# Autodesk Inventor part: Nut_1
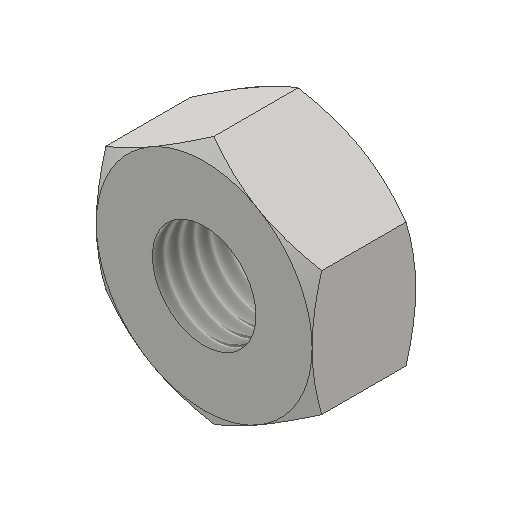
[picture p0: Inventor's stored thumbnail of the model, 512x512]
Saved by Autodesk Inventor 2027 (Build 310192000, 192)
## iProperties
Created: 2016-05
Part Number: Nut_1
Material: Generic
Document SubType Name: Modeling
Designer: CADCIM
Density: 1 g/cm^3
Appearance: Default
Author: CADCIM
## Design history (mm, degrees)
sketch "Sketch1"
  geometry: L1 (0, -14.434)-(-12.5, -7.217); L2 (-12.5, -7.217)-(-12.5, 7.217); L3 (-12.5, 7.217)-(0, 14.434); L4 (0, 14.434)-(12.5, 7.217); L5 (12.5, 7.217)-(12.5, -7.217); L6 (12.5, -7.217)-(0, -14.434); 2 further points
  constraints: 12 end point, 1 coincident, 13 other
  dimensions: "d0" = 25 distance between parallel lines of L2 L5
extrude "Extrusion1" new body sketch "Sketch1" distance "d1" = 12; taper "d2" = 0 deg
sketch "Sketch2"
  geometry: L1 (12.5, -7.217)-(12.5, 7.217) reference; C1 r 12.5 at (0, 0); 1 further point
  constraints: 1 centre point, 1 coincident, 1 tangent
extrude "Extrusion2" sketch "Sketch2" distance "d3" = 16; taper "d4" = 60 deg
sketch "Sketch3"
  geometry: L1 (0, -14.434)-(12.5, -7.217) reference; C1 r 12.5 at (0, 0); 1 further point
  constraints: 1 centre point, 1 coincident, 1 tangent
extrude "Extrusion3" sketch "Sketch3" distance "d5" = 16; taper "d6" = 60 deg
sketch "Sketch5"
  geometry: C1 r 6 at (0, 0); 1 further point
  constraints: 1 centre point, 1 coincident
  dimensions: "d16" = 12 diameter of C1
extrude "Extrusion4" cut sketch "Sketch5" distance "d17" = 48.25; taper "d18" = 0 deg
thread "Thread1" dims "d19" = 16, "d20" = 0
body "Solid1"
